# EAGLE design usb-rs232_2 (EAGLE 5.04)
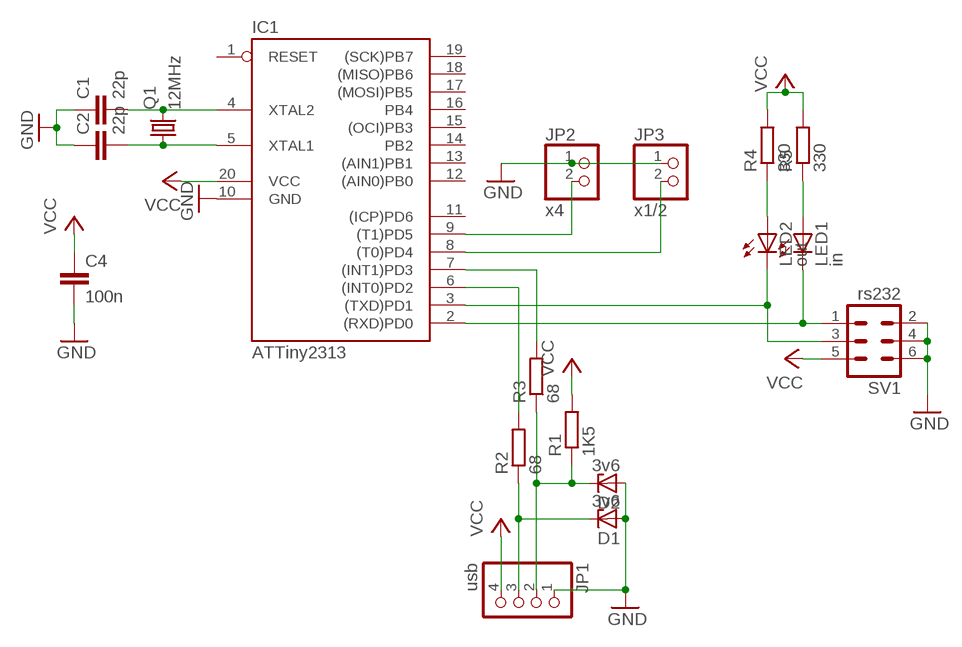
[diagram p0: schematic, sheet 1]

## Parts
C1  22p  C-EUC0805  [C0805]
C2  22p  C-EUC0805  [C0805]
C4  100n  C-EUC1206K  [C1206K]
D1  3v6  ZENER-DIODESMB  [SMB]
D2  3v6  ZENER-DIODESMB  [SMB]
IC1  ATTiny2313  AT90S2313S  [SO20L]
JP1  usb  PINHD-1X4  [1X04]
JP2  x4  PINHD-1X2  [1X02]
JP3  x1/2  PINHD-1X2  [1X02]
LED1  in  LED3MM  [LED3MM]
LED2  out  LED3MM  [LED3MM]
Q1  12MHz  CRYSTALSM49  [SM49]
R1  1K5  R-EU_M1206  [M1206]
R2  68  R-EU_M1206  [M1206]
R3  68  R-EU_M1206  [M1206]
R4  330  R-EU_M1206  [M1206]
R5  330  R-EU_M1206  [M1206]
SV1  rs232  ML6L  [ML6L]

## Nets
GND: C1.1 C2.1 C4.2 D1.A D2.A IC1.10(GND) JP1.1 JP2.1 JP3.1 SV1.2 SV1.4 SV1.6
N$1: D2.C JP1.2 R1.1 R3.1
N$2: IC1.6((INT0)PD2) R2.2
N$3: IC1.7((INT1)PD3) R3.2
N$4: D1.C JP1.3 R2.1
N$5: C1.2 IC1.4(XTAL2) Q1.2
N$6: C2.2 IC1.5(XTAL1) Q1.1
N$7: IC1.9((T1)PD5) JP2.2
N$8: IC1.8((T0)PD4) JP3.2
N$9: LED2.A R4.1
N$10: LED1.A R5.1
N$13: IC1.2((RXD)PD0) LED1.K(C) SV1.1
N$14: IC1.3((TXD)PD1) LED2.K(C) SV1.3
VCC: C4.1 IC1.20(VCC) JP1.4 R1.2 R4.2 R5.2 SV1.5
Unconnected: IC1.1(RESET) IC1.11((ICP)PD6) IC1.12((AIN0)PB0) IC1.13((AIN1)PB1) IC1.14(PB2) IC1.15((OCI)PB3) IC1.16(PB4) IC1.17((MOSI)PB5) IC1.18((MISO)PB6) IC1.19((SCK)PB7)

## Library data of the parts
C1 C2 C4 = rcl:C-EU: CAPACITOR, European symbol
D1 D2 = diode:ZENER-DIODE: Z-Diode
IC1 = atmel:AT90S2313: MICROCONTROLLER 2 Kbytes FLASH 128 bytes SRAM 128 bytes EEPROM UART
JP1 = pinhead:PINHD-1X4: PIN HEADER
JP2 JP3 = pinhead:PINHD-1X2: PIN HEADER
LED1 LED2 = led:LED: LED
Q1 = crystal:CRYSTAL: CRYSTAL
R1-R5 = rcl:R-EU_: RESISTOR, European symbol
SV1 = con-harting-ml:ML6: HARTING

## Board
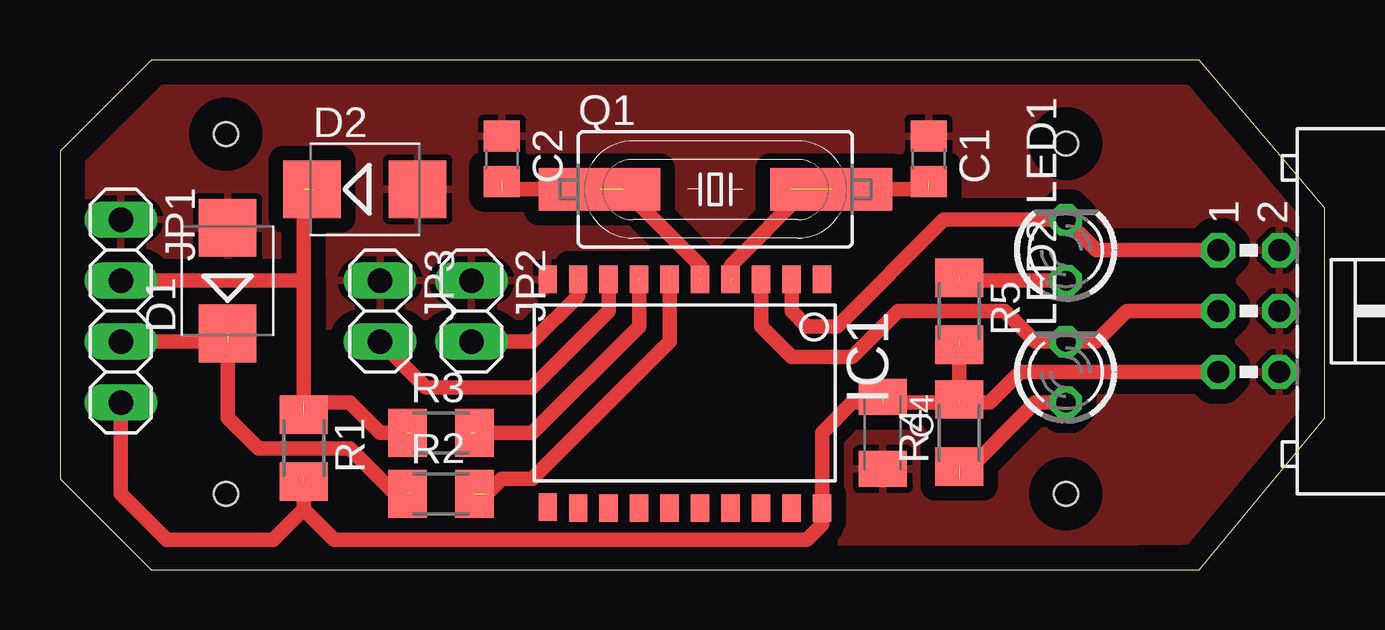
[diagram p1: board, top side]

Size 52.7 x 21.27 mm. Coordinates in mm from the lower left corner, seen from the top.
Outline: 3.81,0 47.46,0 52.7,6.35 52.7,15.09 47.46,21.27 3.81,21.27 0,17.46 0,3.81 3.81,0
Copper layers (1*16): Top 0.035mm / dielectric 1.5mm / Bottom 0.035mm
Design rules "default *": minimum track width 10mil, minimum drill 24mil, track to track 24mil, track to pad 24mil, pad to pad 24mil, via to via 24mil, smd to smd 24mil, copper to edge 40mil, drill to drill 8mil, minimum pad ring 10mil, minimum via ring 8mil, stop-mask expansion 4mil, vias tented up to drill 0mil, thermal gap 10mil
Holes 1 mm at 41.91,17.78 41.91,3.17 6.91,3.17 6.91,18.18

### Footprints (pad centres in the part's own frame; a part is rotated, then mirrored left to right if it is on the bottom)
C0805 = smd 1.3 x 1.5: 1 -0.95,0; 2 0.95,0
C1206K = smd 1.5 x 2: 1 -1.5,0; 2 1.5,0
SMB = smd 2.4 x 2.4: A 2.2,0; C -2.2,0
SO20L = smd 0.762 x 1.143: 1 -5.08,-5.131; 2 -3.81,-5.131; 3 -2.54,-5.131; 4 -1.27,-5.131; 5 0,-5.131; 6 1.27,-5.131; 7 2.54,-5.131; 8 3.81,-5.131; 9 5.08,-5.131; 10 6.35,-5.131; 11 6.35,4.369; 12 5.08,4.394; 13 3.81,4.394; 14 2.54,4.394; 15 1.27,4.394; 16 0,4.394; 17 -1.27,4.394; 18 -2.54,4.394; 19 -3.81,4.394; 20 -5.08,4.394
1X04 = drill 1.016 long: 1 -3.81,0; 2 -1.27,0; 3 1.27,0; 4 3.81,0
1X02 = drill 1.016 long: 1 -1.27,0; 2 1.27,0
LED3MM = drill 0.813 octagon: A -1.27,0; K 1.27,0
SM49 = smd 5.08 x 1.778: 1 -4.826,0; 2 4.826,0
M1206 = smd 1.6 x 2: 1 -1.4,0; 2 1.4,0
ML6L = drill 0.914 octagon: 1 -2.54,-1.27; 2 -2.54,1.27; 3 0,-1.27; 4 0,1.27; 5 2.54,-1.27; 6 2.54,1.27

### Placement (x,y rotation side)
C1  36.2,17.14 270 top
C2  18.41,17.14 270 top
C4  34.29,5.71 270 top
D1  6.98,12.06 90 top
D2  12.7,15.88 0 top
IC1  26.67,6.99 180 top
JP1  2.54,10.79 270 top
JP2  17.15,10.79 270 top
JP3  13.33,10.79 270 top
LED1  41.91,13.34 90 top
LED2  41.91,8.26 90 top
Q1  27.3,15.88 0 top
R1  10.16,5.08 270 top
R2  15.87,3.17 0 top
R3  15.87,5.71 0 top
R4  37.47,5.71 90 top
R5  37.47,10.79 270 top
SV1  49.53,10.79 270 top

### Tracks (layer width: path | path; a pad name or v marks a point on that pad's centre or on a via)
GND
  pour Top: -1.27,20.95 -1.27,0.64 52.07,1.27 52.07,20.95
N$1  (3 unrouted)
  Top 0.61: 14.6,5.71 13.33,5.71 12.06,6.99 10.79,6.99 | 10.79,6.99 10.79,6.35 | 10.79,6.99 10.16,6.99 10.16,12.06 | JP1.2 10.16,12.06 | 10.16,12.06 10.16,15.88
N$2  (2 unrouted)
  Top 0.61: 17.78,3.17 18.41,3.81 19.69,3.81 25.4,9.53 25.4,12.06
N$3  (2 unrouted)
  Top 0.61: 17.15,5.71 19.69,5.71 24.13,10.16 24.13,12.06
N$4  (2 unrouted)
  Top 0.61: 14.6,3.17 13.97,3.17 12.06,5.08 8.26,5.08 6.98,6.35 6.98,9.53 JP1.3
N$5  (4 unrouted)
  Top 0.61: 27.94,12.06 27.94,12.7 31.12,15.88 | 30.48,15.88 36.2,15.88
N$6  (3 unrouted)
  Top 0.61: 26.67,12.06 26.67,12.7 23.49,15.88 18.41,15.88
N$7  (1 unrouted)
  Top 0.61: JP2.2 19.69,9.53 21.59,11.43 21.59,12.06
N$8  (1 unrouted)
  Top 0.61: JP3.2 15.24,7.62 19.69,7.62 22.86,10.79 22.86,12.06
N$9  (1 unrouted)
  Top 0.61: LED2.A 40.64,6.99 37.47,3.81
N$10  (1 unrouted)
  Top 0.61: 37.47,12.06 LED1.A
N$13  (1 unrouted)
  Top 0.61: SV1.1 43.18,13.34 LED1.K 36.83,14.61 32.39,10.16 31.12,10.16 30.48,10.79 30.48,12.06
N$14  (1 unrouted)
  Top 0.61: SV1.3 44.45,10.79 43.18,9.53 LED2.K 40.64,9.53 39.37,10.79 34.93,10.79 33.02,8.89 30.48,8.89 29.21,10.16 29.21,12.06
VCC  (5 unrouted)
  Top 0.61: 10.16,2.54 11.43,1.27 31.12,1.27 31.75,1.91 31.75,2.54 31.75,5.71 33.02,6.99 34.29,6.99 37.47,6.99 | 37.47,6.99 38.73,6.99 40.01,8.26 SV1.5 | JP1.4 2.54,3.17 4.45,1.27 8.89,1.27 10.16,2.54 | 10.16,2.54 10.16,3.81 | 37.47,6.99 37.47,9.53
